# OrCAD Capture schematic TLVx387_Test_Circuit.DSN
size A; title: TLVx387 High Precision, Zero-Drift, Low-Input-Bias-Current; rev: 1.0; note: Datasheet: SBOSA91  EVM: N/A
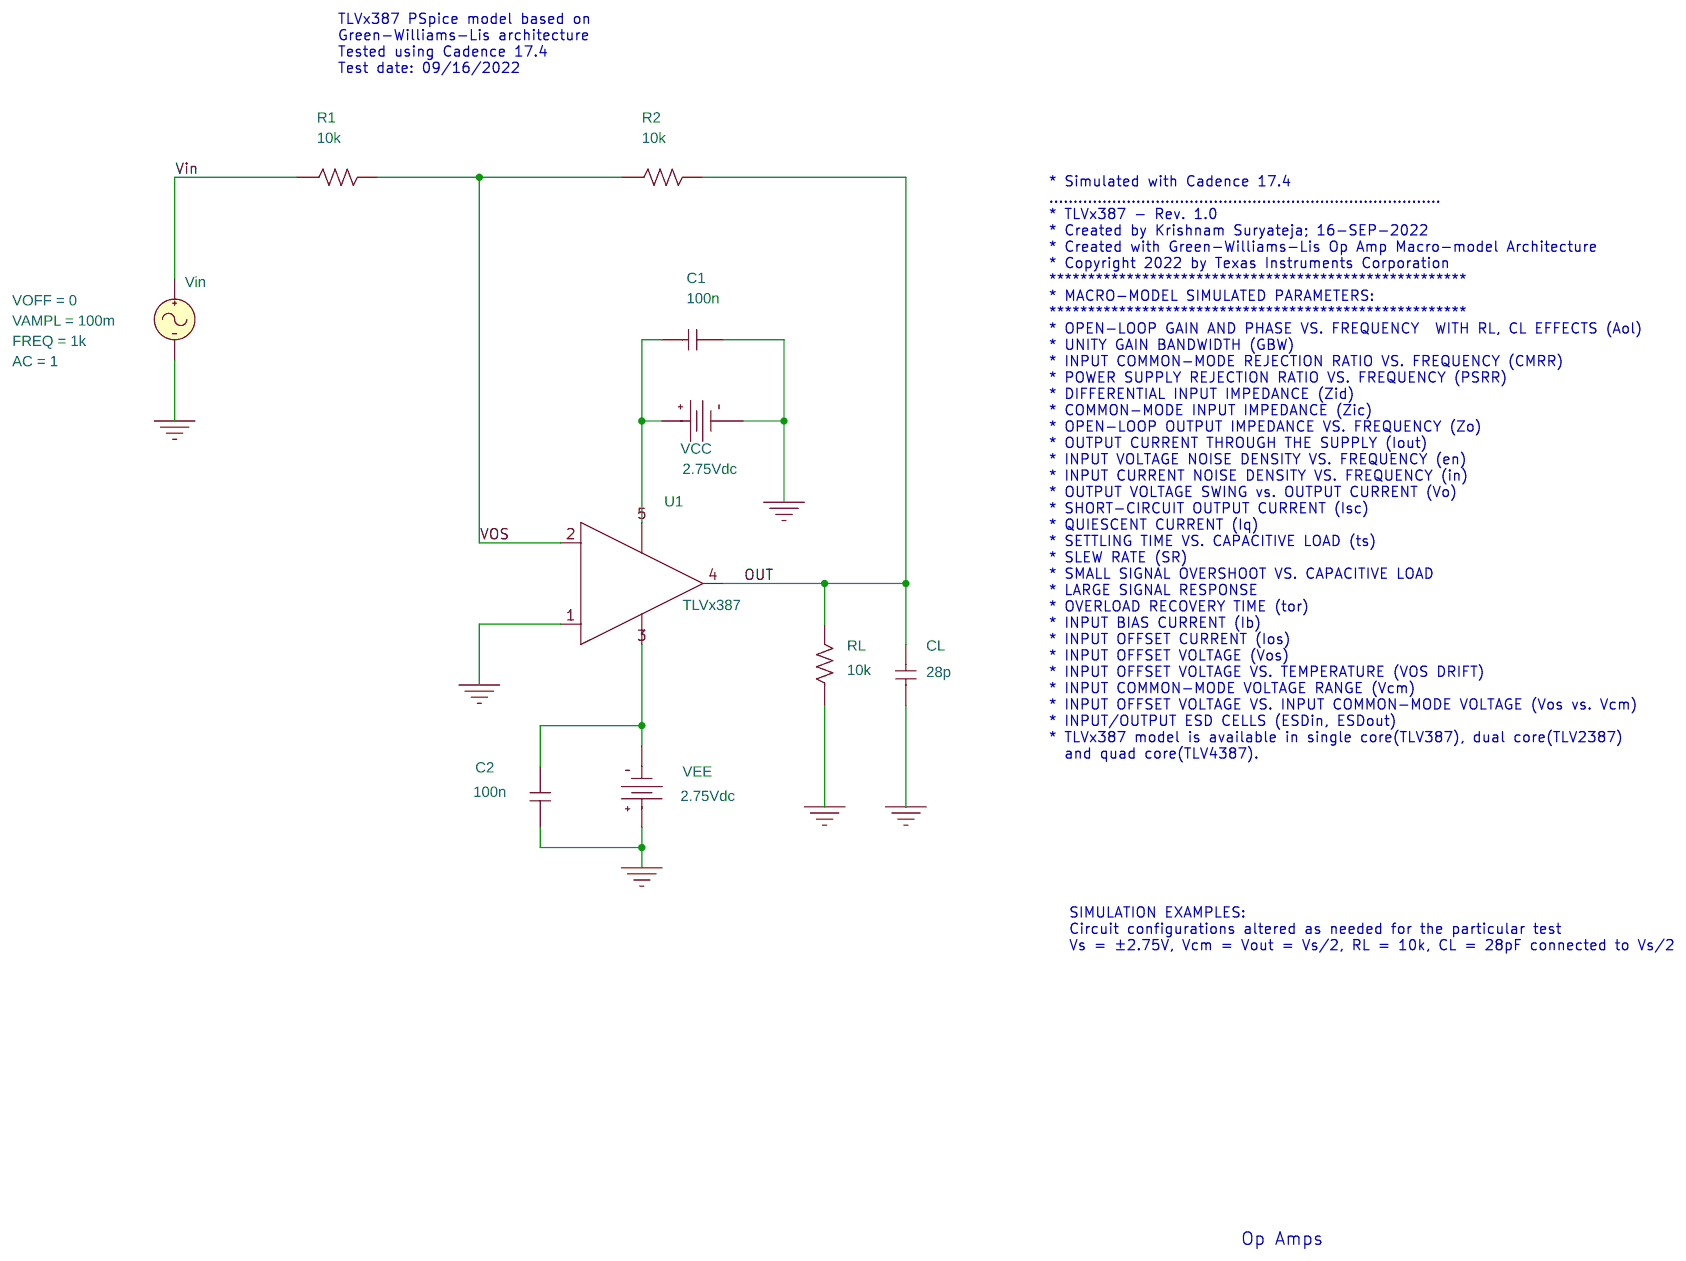
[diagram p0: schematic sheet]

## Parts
C1  100n  [cap196]
C2  100n  [cap196]
CL  28p  [cap196]
R1  10k  [AXRC05]
R2  10k  [AXRC05]
RL  10k  [AXRC05]
U1  TLVx387
VCC  VDC
VEE  VDC
Vin  VSIN

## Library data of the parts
C1 C2 CL = C
R1 R2 RL = R
U1 = TLVx387
VCC VEE = VDC: DC: 2.75Vdc
Vin = VSIN: AC: 1; FREQ: 1k; VAMPL: 100m; VOFF: 0

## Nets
Vin: R1.1 Vin.1(+)
0: C1.2 C2.1 CL.2 RL.1 U1.1(+) VCC.1(-) VEE.0(+) Vin.2(-)
OUT: CL.1 R2.2 RL.2 U1.4(OUT)
VOS: R1.2 R2.1 U1.2(-)
N27303: C1.1 U1.5(V+) VCC.0(+)
N27354: C2.2 U1.3(V-) VEE.1(-)

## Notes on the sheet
- TLVx387 PSpice model based on
  Green-Williams-Lis architecture
  Tested using Cadence 17.4
  Test date: 09/16/2022
- * Simulated with Cadence 17.4
  .................................................................................
  * TLVx387 - Rev. 1.0
  * Created by Krishnam Suryateja; 16-SEP-2022
  * Created with Green-Williams-Lis Op Amp Macro-model Architecture
  * Copyright 2022 by Texas Instruments Corporation
  ******************************************************
  * MACRO-MODEL SIMULATED PARAMETERS:
  ******************************************************
  * OPEN-LOOP GAIN AND PHASE VS. FREQUENCY  WITH RL, CL EFFECTS (Aol)
  * UNITY GAIN BANDWIDTH (GBW)
  * INPUT COMMON-MODE REJECTION RATIO VS. FREQUENCY (CMRR)
  * POWER SUPPLY REJECTION RATIO VS. FREQUENCY (PSRR)
  * DIFFERENTIAL INPUT IMPEDANCE (Zid)
  * COMMON-MODE INPUT IMPEDANCE (Zic)
  * OPEN-LOOP OUTPUT IMPEDANCE VS. FREQUENCY (Zo)
  * OUTPUT CURRENT THROUGH THE SUPPLY (Iout)
  * INPUT VOLTAGE NOISE DENSITY VS. FREQUENCY (en)
  * INPUT CURRENT NOISE DENSITY VS. FREQUENCY (in)
  * OUTPUT VOLTAGE SWING vs. OUTPUT CURRENT (Vo)
  * SHORT-CIRCUIT OUTPUT CURRENT (Isc)
  * QUIESCENT CURRENT (Iq)
  * SETTLING TIME VS. CAPACITIVE LOAD (ts)
  * SLEW RATE (SR)
  * SMALL SIGNAL OVERSHOOT VS. CAPACITIVE LOAD
  * LARGE SIGNAL RESPONSE
  * OVERLOAD RECOVERY TIME (tor)
  * INPUT BIAS CURRENT (Ib)
  * INPUT OFFSET CURRENT (Ios)
  * INPUT OFFSET VOLTAGE (Vos)
  * INPUT OFFSET VOLTAGE VS. TEMPERATURE (VOS DRIFT)
  * INPUT COMMON-MODE VOLTAGE RANGE (Vcm)
  * INPUT OFFSET VOLTAGE VS. INPUT COMMON-MODE VOLTAGE (Vos vs. Vcm)
  * INPUT/OUTPUT ESD CELLS (ESDin, ESDout)
  * TLVx387 model is available in single core(TLV387), dual core(TLV2387)
    and quad core(TLV4387).
- SIMULATION EXAMPLES:
  Circuit configurations altered as needed for the particular test
  Vs = ±2.75V, Vcm = Vout = Vs/2, RL = 10k, CL = 28pF connected to Vs/2
- Op Amps
